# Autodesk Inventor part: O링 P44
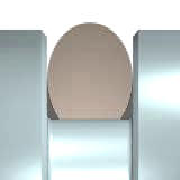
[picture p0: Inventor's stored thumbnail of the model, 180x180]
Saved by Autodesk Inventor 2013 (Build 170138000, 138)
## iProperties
Created: 2012-02
Part Number: O링 P44
Material: 고무
Description: O-링
Document SubType Name: Modeling
Standard: JIS 2406
Designer: mdu-01
Standards Organization: JIS
Language: ko-KR
Size Designation: P44
Categories: <MemberInstance><Categories><Category DisplayName="샤프트 부품" InternalName="7f7aeb1f-a693-4053-b835-cee3144e0d98" Mnemonic="SHFT"><Category DisplayName="실링" Intern
Density: 0.93 g/cm^3
IsCustomPart: 1
Author: mdu-01
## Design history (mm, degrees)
revolve "본체" stored, may be unused: angle "d19" = 90 deg
body "Solid1"
sketch "스케치1"
  geometry: L1 (-0.901, 0)-(0.901, 0); L2 (-2.412, 0)-(3.006, 0) reference; L3 (0.901, -3)-(-0.901, -3); L4 (-1.638, -25)-(2.232, -25); L5 (0, 1.8)-(0, -10.8) reference; L6 (0, 0)-(0, 0); A1 r 1.75 centre (0, -1.5) between (-0.901, 0) and (-0.901, -3); A2 r 1.75 centre (0, -1.5) between (0.901, -3) and (0.901, 0)
  constraints: 8 end point, 4 point on circle, 4 point on line, 2 centre point, 2 parallel, 1 coincident, 1 horizontal, 1 horizontal alignment, 1 vertical alignment, 1 other
  dimensions: "d0" = 44 diameter of L3 L4 (= NDOR); "d1" = 1.5 distance from line of L3 A1.centre (= -0.25 x NDOR + 0.25 x NND); "d2" = 50 diameter of L2 L4 (= NND); "d3" = 1.75 radius of A1 (= 0.5 x QDM)
other parameters: "QDM" = 3.5 [user parameter; used in 1 equation term], "NND" = 50 [user parameter; used in 3 equation terms], "NDOR" = 44 [user parameter; used in 3 equation terms], "d4" = 0, "d26" = 0, "R2" = 0.2 [user parameter], "SD1" = 43.7 [user parameter], "R1" = 0.7 [user parameter], "NB2" = 6 [user parameter], "NB1" = 4.7 [user parameter], "NB3" = 7.8 [user parameter], "BD" = 49.85 [user parameter], "NTOR" = 3 (= -0.5 x NDOR + 0.5 x NND) [user parameter]
